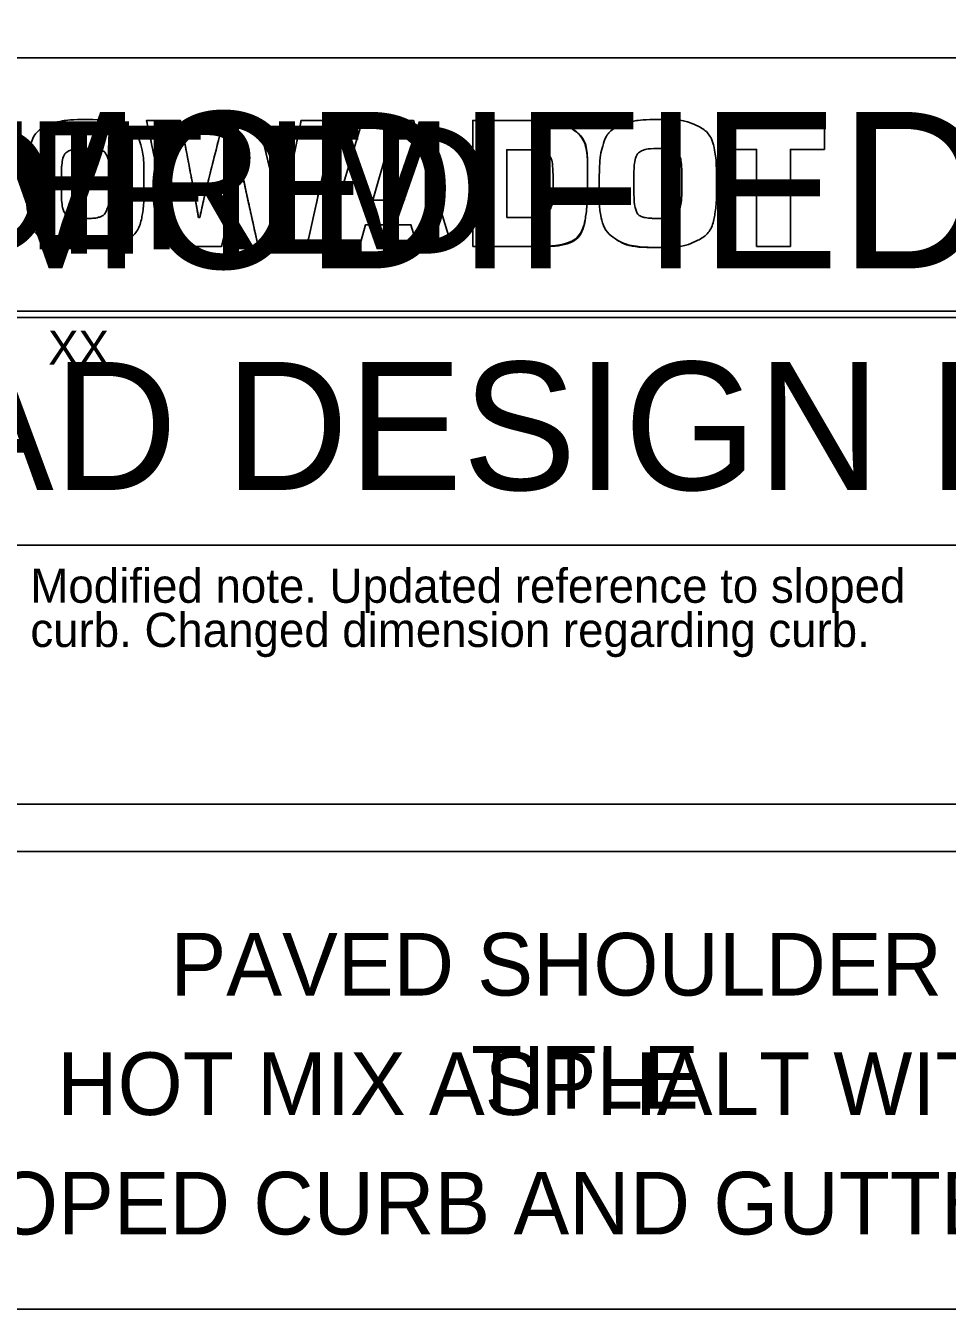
# Model space of a CAD drawing. Extents: x 10133 to 81668, y 2357 to 12713.
# Drawn here: x 12847.5 to 13171.6, y 4251.2 to 4702.6 of the extents above; entities that cross this region are included whole.
import ezdxf

# ---------------------------------------------------------------- set-up
doc = ezdxf.new("R2010")
doc.units = 0
for name, color, linetype in [('dsnDOTLogo', 7, 'Continuous'), ('dsnNonPlotable', 7, 'Continuous'), ('dsnStdBlock', 7, 'Continuous'), ('dsnStdBlockInterim', 7, 'Continuous'), ('dsnStdBlockModified', 7, 'Continuous'), ('dsnStdBorder', 7, 'Continuous'), ('dsnstdModifiedBlock', 7, 'Continuous')]:
    doc.layers.add(name, color=color, linetype=linetype)

msp = doc.modelspace()

# ---------------------------------------------------------------- linework, layer by layer
at = {"layer": 'dsnDOTLogo'}
for p, q in [((12899.44, 4624.93), (12889.97, 4669.23)), ((12889.97, 4669.23), (12901.88, 4669.23)), ((12901.88, 4669.23), (12905.16, 4652.16)), ((12910.6, 4643.62), (12917.03, 4669.23)), ((12917.03, 4669.23), (12929.26, 4669.23)), ((12929.26, 4669.23), (12933.35, 4652.16)), ((12940.84, 4652.16), (12944.32, 4669.23)), ((12944.32, 4669.23), (12956.19, 4669.23)), ((12956.19, 4669.23), (12946.32, 4624.93)), ((13004.72, 4624.93), (13004.72, 4669.23)), ((13004.72, 4669.23), (13027.88, 4669.23)), ((13026.28, 4658.91), (13016.66, 4658.91)), ((13016.66, 4658.91), (13016.66, 4635.12)), ((12923.25, 4652.67), (12922.8, 4652.68)), ((12940.65, 4651.25), (12940.84, 4652.16)), ((13045.05, 4652.71), (13045.05, 4647.42)), ((12908.69, 4635.09), (12910.6, 4643.62)), ((12908.23, 4635.09), (12908.69, 4635.09)), ((12919.7, 4638.82), (12916.35, 4624.93)), ((12929.25, 4624.93), (12926.17, 4638.83)), ((12937.18, 4635.09), (12937.63, 4635.09)), ((13016.66, 4635.12), (13026.24, 4635.12)), ((12916.35, 4624.93), (12899.44, 4624.93)), ((12946.32, 4624.93), (12929.25, 4624.93)), ((13027.27, 4624.93), (13004.72, 4624.93))]:
    msp.add_line(p, q, dxfattribs=at)
for points in [[(12997.32, 4624.93), (12983.86, 4669.23), (12965.88, 4669.23), (12952.58, 4624.93), (12964.91, 4624.93), (12967.03, 4632.56), (12982.96, 4632.56), (12985.25, 4624.93), (12997.32, 4624.93)], [(12982.96, 4632.56), (12967.03, 4632.56), (12964.91, 4624.93), (12952.58, 4624.93), (12965.88, 4669.23), (12983.86, 4669.23), (12997.32, 4624.93), (12985.25, 4624.93), (12982.96, 4632.56)], [(13116.47, 4624.93), (13116.47, 4659.04), (13128.41, 4659.04), (13128.41, 4669.23), (13093.34, 4669.23), (13093.34, 4659.04), (13104.53, 4659.04), (13104.53, 4624.93), (13116.47, 4624.93)], [(13116.47, 4659.04), (13116.47, 4624.93), (13104.53, 4624.93), (13104.53, 4659.04), (13093.34, 4659.04), (13093.34, 4669.23), (13128.41, 4669.23), (13128.41, 4659.04), (13116.47, 4659.04)], [(12969.61, 4641.16), (12975.05, 4660.38), (12980.66, 4641.16), (12969.61, 4641.16)], [(12980.66, 4641.16), (12975.05, 4660.38), (12969.61, 4641.16), (12980.66, 4641.16)]]:
    msp.add_lwpolyline(points, dxfattribs=at)
for points, degree in [([(12869.15, 4669.55), (12874.6, 4669.55), (12878.49, 4669.04), (12880.83, 4668.02), (12884.98, 4666.21), (12887.53, 4662.97), (12888.49, 4658.32), (12888.88, 4656.42), (12889.07, 4652.59), (12889.07, 4646.84), (12889.07, 4642.01), (12888.92, 4638.71), (12888.62, 4636.94), (12887.75, 4631.88), (12885.35, 4628.43), (12881.41, 4626.59), (12878.6, 4625.27), (12874.01, 4624.61), (12867.66, 4624.61), (12861.49, 4624.61), (12857.1, 4625.41), (12854.48, 4627.01), (12851.15, 4629.06), (12849.09, 4632.13), (12848.32, 4636.19), (12847.99, 4637.9), (12847.83, 4640.75), (12847.83, 4644.73), (12847.83, 4652.17), (12848.22, 4657.28), (12849, 4660.07), (12850.08, 4663.95), (12852.92, 4666.69), (12857.53, 4668.32), (12859.82, 4669.14), (12863.7, 4669.55), (12869.15, 4669.55)], 3), ([(12860.95, 4625.01), (12858.18, 4625.4), (12856.02, 4626.07), (12854.48, 4627.01), (12851.15, 4629.06), (12849.09, 4632.13), (12848.32, 4636.19), (12847.99, 4637.9), (12847.83, 4640.75), (12847.83, 4644.73), (12847.83, 4652.17), (12848.22, 4657.28), (12849, 4660.07), (12850.08, 4663.95), (12852.92, 4666.69), (12857.53, 4668.32), (12859.82, 4669.14), (12863.7, 4669.55), (12869.15, 4669.55)], 3), ([(12869.15, 4669.55), (12874.6, 4669.55), (12878.49, 4669.04), (12880.83, 4668.02), (12884.98, 4666.21), (12887.53, 4662.97), (12888.49, 4658.32), (12888.88, 4656.42), (12889.07, 4652.59), (12889.07, 4646.84), (12889.07, 4642.01), (12888.92, 4638.71), (12888.62, 4636.94), (12887.75, 4631.88), (12885.35, 4628.43), (12881.41, 4626.59), (12878.6, 4625.27), (12874.01, 4624.61), (12867.66, 4624.61), (12865.12, 4624.61), (12862.89, 4624.74), (12860.95, 4625.01)], 3), ([(12956.19, 4669.23), (12956.19, 4669.23), (12946.32, 4624.93), (12946.32, 4624.93), (12946.32, 4624.93), (12929.25, 4624.93), (12929.25, 4624.93), (12929.25, 4624.93), (12926.17, 4638.83), (12926.17, 4638.83), (12925.23, 4643), (12924.25, 4647.61), (12923.25, 4652.67), (12923.25, 4652.67), (12922.8, 4652.68), (12922.8, 4652.68), (12922.48, 4651.25), (12922.24, 4650.09), (12922.07, 4649.2), (12921.68, 4647.23), (12920.89, 4643.77), (12919.7, 4638.82), (12919.7, 4638.82), (12916.35, 4624.93), (12916.35, 4624.93), (12916.35, 4624.93), (12899.44, 4624.93), (12899.44, 4624.93), (12899.44, 4624.93), (12889.97, 4669.23), (12889.97, 4669.23), (12889.97, 4669.23), (12901.88, 4669.23), (12901.88, 4669.23), (12901.88, 4669.23), (12905.16, 4652.16), (12905.16, 4652.16), (12906.31, 4646.17), (12907.33, 4640.48), (12908.23, 4635.09), (12908.23, 4635.09), (12908.69, 4635.09), (12908.69, 4635.09), (12908.69, 4635.09), (12910.6, 4643.62), (12910.6, 4643.62), (12910.6, 4643.62), (12917.03, 4669.23), (12917.03, 4669.23), (12917.03, 4669.23), (12929.26, 4669.23), (12929.26, 4669.23), (12929.26, 4669.23), (12933.35, 4652.16), (12933.35, 4652.16), (12934.67, 4646.66), (12935.94, 4640.97), (12937.18, 4635.09), (12937.18, 4635.09), (12937.63, 4635.09), (12937.63, 4635.09), (12938.56, 4640.48), (12939.57, 4645.86), (12940.65, 4651.25), (12940.65, 4651.25), (12940.84, 4652.16), (12940.84, 4652.16), (12940.84, 4652.16), (12944.32, 4669.23), (12944.32, 4669.23), (12944.32, 4669.23), (12956.19, 4669.23), (12956.19, 4669.23)], 3), ([(13004.72, 4624.93), (13004.72, 4624.93), (13004.72, 4669.23), (13004.72, 4669.23), (13004.72, 4669.23), (13027.88, 4669.23), (13027.88, 4669.23), (13032.48, 4669.23), (13036.03, 4668.47), (13038.54, 4666.95), (13042.97, 4664.29), (13045.14, 4659.54), (13045.05, 4652.71), (13045.05, 4652.71), (13045.05, 4647.42), (13045.05, 4647.42), (13044.99, 4641.99), (13044.82, 4638.33), (13044.56, 4636.45), (13043.53, 4628.77), (13037.76, 4624.93), (13027.27, 4624.93), (13027.27, 4624.93), (13004.72, 4624.93), (13004.72, 4624.93)], 3), ([(13027.88, 4669.23), (13032.48, 4669.23), (13036.03, 4668.47), (13038.54, 4666.95), (13042.97, 4664.29), (13045.14, 4659.54), (13045.05, 4652.71)], 3), ([(13070.52, 4669.55), (13075.98, 4669.55), (13079.87, 4669.04), (13082.21, 4668.02), (13086.36, 4666.21), (13088.91, 4662.97), (13089.86, 4658.32), (13090.25, 4656.42), (13090.45, 4652.59), (13090.45, 4646.84), (13090.45, 4642.01), (13090.29, 4638.71), (13089.99, 4636.94), (13089.13, 4631.88), (13086.73, 4628.43), (13082.79, 4626.59), (13079.98, 4625.27), (13075.39, 4624.61), (13069.03, 4624.61), (13062.87, 4624.61), (13058.47, 4625.41), (13055.86, 4627.01), (13052.53, 4629.06), (13050.47, 4632.13), (13049.69, 4636.19), (13049.37, 4637.9), (13049.2, 4640.75), (13049.2, 4644.73), (13049.2, 4652.17), (13049.59, 4657.28), (13050.37, 4660.07), (13051.45, 4663.95), (13054.3, 4666.69), (13058.91, 4668.32), (13061.2, 4669.14), (13065.07, 4669.55), (13070.52, 4669.55)], 3), ([(13062.33, 4625.01), (13059.56, 4625.4), (13057.4, 4626.07), (13055.86, 4627.01), (13052.53, 4629.06), (13050.47, 4632.13), (13049.69, 4636.19), (13049.37, 4637.9), (13049.2, 4640.75), (13049.2, 4644.73), (13049.2, 4652.17), (13049.59, 4657.28), (13050.37, 4660.07), (13051.45, 4663.95), (13054.3, 4666.69), (13058.91, 4668.32), (13061.2, 4669.14), (13065.07, 4669.55), (13070.52, 4669.55)], 3), ([(13070.52, 4669.55), (13075.98, 4669.55), (13079.87, 4669.04), (13082.21, 4668.02), (13086.36, 4666.21), (13088.91, 4662.97), (13089.86, 4658.32), (13090.25, 4656.42), (13090.45, 4652.59), (13090.45, 4646.84), (13090.45, 4642.01), (13090.29, 4638.71), (13089.99, 4636.94), (13089.13, 4631.88), (13086.73, 4628.43), (13082.79, 4626.59), (13079.98, 4625.27), (13075.39, 4624.61), (13069.03, 4624.61), (13066.5, 4624.61), (13064.26, 4624.74), (13062.33, 4625.01)], 3), ([(12868.79, 4659.36), (12866.04, 4659.38), (12864.16, 4659.18), (12863.14, 4658.74), (12861.48, 4658.05), (12860.47, 4656.21), (12860.13, 4653.23), (12860.06, 4652.73), (12860.03, 4650.46), (12860.03, 4646.41), (12860.03, 4641.85), (12860.29, 4638.89), (12860.81, 4637.52), (12861.31, 4636.25), (12862.43, 4635.42), (12864.18, 4635.06), (12865, 4634.88), (12866.5, 4634.8), (12868.66, 4634.8), (12870.74, 4634.8), (12872.19, 4634.92), (12873.01, 4635.15), (12874.46, 4635.59), (12875.47, 4636.53), (12876.04, 4637.99), (12876.62, 4639.45), (12876.9, 4642.64), (12876.9, 4647.55), (12876.9, 4652.37), (12876.63, 4655.41), (12876.09, 4656.65), (12875.55, 4657.9), (12874.51, 4658.7), (12872.98, 4659.07), (12872.2, 4659.26), (12870.8, 4659.36), (12868.79, 4659.36)], 3), ([(12868.79, 4659.36), (12866.04, 4659.38), (12864.16, 4659.18), (12863.14, 4658.74), (12861.48, 4658.05), (12860.47, 4656.21), (12860.13, 4653.23), (12860.06, 4652.73), (12860.03, 4650.46), (12860.03, 4646.41), (12860.03, 4641.85), (12860.29, 4638.89), (12860.81, 4637.52), (12861.31, 4636.25), (12862.43, 4635.42), (12864.18, 4635.06), (12865, 4634.88), (12866.5, 4634.8), (12868.66, 4634.8), (12870.74, 4634.8), (12872.19, 4634.92), (12873.01, 4635.15), (12874.46, 4635.59), (12875.47, 4636.53), (12876.04, 4637.99), (12876.62, 4639.45), (12876.9, 4642.64), (12876.9, 4647.55), (12876.9, 4652.37), (12876.63, 4655.41), (12876.09, 4656.65), (12875.55, 4657.9), (12874.51, 4658.7), (12872.98, 4659.07), (12872.2, 4659.26), (12870.8, 4659.36), (12868.79, 4659.36)], 3), ([(13016.66, 4635.12), (13016.66, 4635.12), (13026.24, 4635.12), (13026.24, 4635.12), (13028.94, 4635.12), (13030.78, 4635.98), (13031.75, 4637.68), (13032.55, 4639.09), (13032.95, 4642.43), (13032.95, 4647.71), (13032.95, 4652.51), (13032.56, 4655.54), (13031.78, 4656.8), (13030.9, 4658.2), (13029.06, 4658.91), (13026.28, 4658.91), (13026.28, 4658.91), (13016.66, 4658.91), (13016.66, 4658.91), (13016.66, 4658.91), (13016.66, 4635.12), (13016.66, 4635.12)], 3), ([(13026.24, 4635.12), (13028.94, 4635.12), (13030.78, 4635.98), (13031.75, 4637.68), (13032.55, 4639.09), (13032.95, 4642.43), (13032.95, 4647.71), (13032.95, 4652.51), (13032.56, 4655.54), (13031.78, 4656.8), (13030.9, 4658.2), (13029.06, 4658.91), (13026.28, 4658.91)], 3), ([(13070.17, 4659.36), (13067.42, 4659.38), (13065.54, 4659.18), (13064.52, 4658.74), (13062.85, 4658.05), (13061.85, 4656.21), (13061.5, 4653.23), (13061.44, 4652.73), (13061.41, 4650.46), (13061.41, 4646.41), (13061.41, 4641.85), (13061.66, 4638.89), (13062.18, 4637.52), (13062.68, 4636.25), (13063.81, 4635.42), (13065.56, 4635.06), (13066.38, 4634.88), (13067.87, 4634.8), (13070.04, 4634.8), (13072.11, 4634.8), (13073.56, 4634.92), (13074.39, 4635.15), (13075.83, 4635.59), (13076.85, 4636.53), (13077.42, 4637.99), (13077.99, 4639.45), (13078.28, 4642.64), (13078.28, 4647.55), (13078.28, 4652.37), (13078.01, 4655.41), (13077.47, 4656.65), (13076.93, 4657.9), (13075.89, 4658.7), (13074.35, 4659.07), (13073.57, 4659.26), (13072.18, 4659.36), (13070.17, 4659.36)], 3), ([(13070.17, 4659.36), (13067.42, 4659.38), (13065.54, 4659.18), (13064.52, 4658.74), (13062.85, 4658.05), (13061.85, 4656.21), (13061.5, 4653.23), (13061.44, 4652.73), (13061.41, 4650.46), (13061.41, 4646.41), (13061.41, 4641.85), (13061.66, 4638.89), (13062.18, 4637.52), (13062.68, 4636.25), (13063.81, 4635.42), (13065.56, 4635.06), (13066.38, 4634.88), (13067.87, 4634.8), (13070.04, 4634.8), (13072.11, 4634.8), (13073.56, 4634.92), (13074.39, 4635.15), (13075.83, 4635.59), (13076.85, 4636.53), (13077.42, 4637.99), (13077.99, 4639.45), (13078.28, 4642.64), (13078.28, 4647.55), (13078.28, 4652.37), (13078.01, 4655.41), (13077.47, 4656.65), (13076.93, 4657.9), (13075.89, 4658.7), (13074.35, 4659.07), (13073.57, 4659.26), (13072.18, 4659.36), (13070.17, 4659.36)], 3), ([(12905.16, 4652.16), (12906.31, 4646.17), (12907.33, 4640.48), (12908.23, 4635.09)], 2), ([(12922.8, 4652.68), (12922.48, 4651.25), (12922.24, 4650.09), (12922.07, 4649.2), (12921.68, 4647.23), (12920.89, 4643.77), (12919.7, 4638.82)], 3), ([(12926.17, 4638.83), (12925.23, 4643), (12924.25, 4647.61), (12923.25, 4652.67)], 2), ([(12933.35, 4652.16), (12934.67, 4646.66), (12935.94, 4640.97), (12937.18, 4635.09)], 2), ([(12937.63, 4635.09), (12938.56, 4640.48), (12939.57, 4645.86), (12940.65, 4651.25)], 2), ([(13045.05, 4647.42), (13044.99, 4641.99), (13044.82, 4638.33), (13044.56, 4636.45), (13043.53, 4628.77), (13037.76, 4624.93), (13027.27, 4624.93)], 3)]:
    msp.add_open_spline(points, degree=degree, dxfattribs=at)
at = {"layer": 'dsnNonPlotable'}
msp.add_lwpolyline([(12697.77, 4691.26), (13385.79, 4691.26), (13385.79, 4251.25), (12697.77, 4251.25)], close=True, dxfattribs=at)
at = {"layer": 'dsnStdBlock'}
for p, q in [((12697.79, 4599.91), (13174.89, 4599.91)), ((12697.79, 4519.91), (13385.81, 4519.91)), ((12697.79, 4428.9), (13385.81, 4428.9))]:
    msp.add_line(p, q, dxfattribs=at)
msp.add_lwpolyline([(12697.79, 4691.25), (13385.81, 4691.25), (13385.81, 4251.24), (12697.79, 4251.24)], close=True, dxfattribs=at)
at = {"layer": 'dsnStdBorder'}
msp.add_lwpolyline([(10250.81, 6261.24), (13385.81, 6261.24), (13385.81, 4251.24), (10250.81, 4251.24)], close=True, dxfattribs=at)
at = {"layer": 'dsnstdModifiedBlock'}
for p, q in [((12697.79, 4602.16), (13385.81, 4602.16)), ((12697.79, 4412.15), (13385.81, 4412.15))]:
    msp.add_line(p, q, dxfattribs=at)
msp.add_lwpolyline([(12697.79, 4691.25), (13385.81, 4691.25), (13385.81, 4251.24), (12697.79, 4251.24)], close=True, dxfattribs=at)

# ---------------------------------------------------------------- texts
at = {"layer": 'dsnStdBlock'}
for s, height, p in [('ROAD DESIGN DETAIL', 45.0011, (12726.92, 4539.33)), ('Modified note. Updated reference to sloped', 12, (12849.11, 4499.65)), ('curb. Changed dimension regarding curb.', 12, (12849.11, 4484.12)), ('PAVED SHOULDER', 22, (12898.39, 4361.57)), ('HOT MIX ASPHALT WITH', 22, (12858.56, 4319.57)), ('6" SLOPED CURB AND GUTTER UNIT', 22, (12764.99, 4277.57))]:
    msp.add_text(s, height=height, dxfattribs=at).set_placement(p)
at = {"layer": 'dsnStdBlockInterim'}
msp.add_text('INTERIM', height=45.001, dxfattribs=at).set_placement((12750.46, 4623.97))
at = {"layer": 'dsnStdBlockModified'}
msp.add_text('MODIFIED', height=45.001, dxfattribs=at).set_placement((12717.49, 4622.41))
at = {"layer": 'dsnstdModifiedBlock'}
for s, height, p in [('MODIFIED', 55, (12827.2, 4617.25)), ('XX', 12, (12855.34, 4583.32)), ('TITLE', 22, (13004.19, 4321.82))]:
    msp.add_text(s, height=height, dxfattribs=at).set_placement(p)

doc.saveas('drawing.dxf')
